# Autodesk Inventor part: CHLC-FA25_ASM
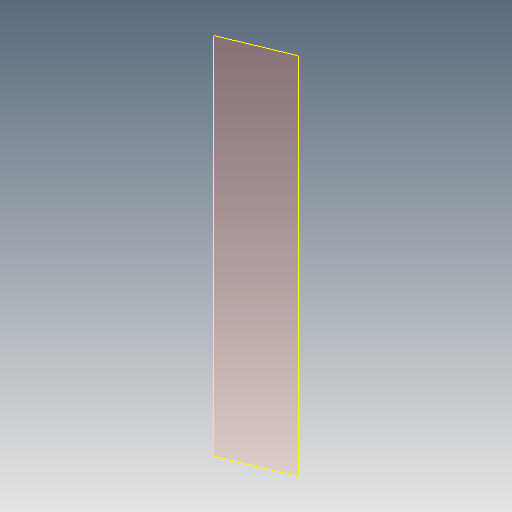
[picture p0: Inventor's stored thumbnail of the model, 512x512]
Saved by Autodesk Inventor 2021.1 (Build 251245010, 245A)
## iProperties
Created: 2021-05
Part Number: CHLC-FA25_ASM
Material: Ogólny
Document SubType Name: Modeling
Designer: user
Density: 1 g/cm^3
Appearance: Domyślna
Author: user
Revision Number: ÈÎºÎ
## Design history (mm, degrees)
feature "Złożony1"
body "Srf1"
